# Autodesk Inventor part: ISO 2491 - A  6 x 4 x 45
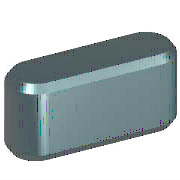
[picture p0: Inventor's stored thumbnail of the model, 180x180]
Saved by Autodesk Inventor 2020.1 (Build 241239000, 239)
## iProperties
Created: 2019-01
Part Number: ISO 2491 - A  6 x 4 x 45
Material: Stahl, weich
Description: Passfedern
Document SubType Name: Modeling
Standard: ISO 2491
Designer: lutzd
Standard Revision: First edition 1974-08-15
Standards Organization: ISO
Language: de-DE
Size Designation: A  6 x 4 x 45
Categories: <MemberInstance><Categories><Category DisplayName="Wellenteile" InternalName="7f7aeb1f-a693-4053-b835-cee3144e0d98" Mnemonic="SHFT"><Category DisplayName="Passf
Mass: 8.11482 g
Surface Area: 8.66144 cm^2
Volume: 1.03374 cm^3
Density: 7.85 g/cm^3
Appearance: Semi-Polished(8)
IsCustomPart: 0
Author: lutzd
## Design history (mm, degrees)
workplane "Work Plane1"
workplane "Work Plane2"
sketch "Skizze1"
  geometry: L1 (3, 3)-(42, 3); L2 (42, -3)-(3, -3); L3 (0, 9.4)-(0, -7.4) reference; L4 (-5, 0)-(30, 0) reference; L5 (45, 0)-(45, 7); A1 r 3 centre (3, 0) between (3, 3) and (3, -3); A2 r 3 centre (42, 0) between (42, -3) and (42, 3)
  constraints: 6 end point, 5 point on circle, 4 tangent, 3 point on line, 2 centre point, 1 horizontal, 1 parallel, 1 perpendicular
  dimensions: "d0" = 3 radius of A1 (= 0.5 x PB); "d13" = 3 radius of A2 (= 0.5 x PB); "d14" = 45 distance between parallel lines of L5 L3 (= NLG)
extrude "Körper1" new body sketch "Skizze1" taper "d3" = 0 deg; stored distance "d4" = 10
workplane "Work Plane3"
body "Solid1"
chamfer "Fase1" distance "d8" = 0.4 (= PHH); stored, may be unused: second distance "d9" = 0.4 (= PHH), angle "d15" = 45 deg
other parameters: "d1" = -2.5 (= -PNT), "d2" = 1.5 (= PH - PNT), "NLG" = 45 [user parameter; used in 1 equation term], "PB" = 6 [user parameter; used in 2 equation terms], "PNT" = 2.5 [user parameter; used in 2 equation terms], "PH" = 4 [user parameter; used in 1 equation term], "PHH" = 0.4 [user parameter; used in 2 equation terms], "d10" = 0, "d16" = 0, "d17" = 0, "d18" = 0, "RR" = 0.16 [user parameter], "WDMIN" = 17 [user parameter], "WDMAX" = 22 [user parameter], "PLB1" = 45 [user parameter], "PLB2" = 45 [user parameter], "PUEB" = 1.8 [user parameter]
